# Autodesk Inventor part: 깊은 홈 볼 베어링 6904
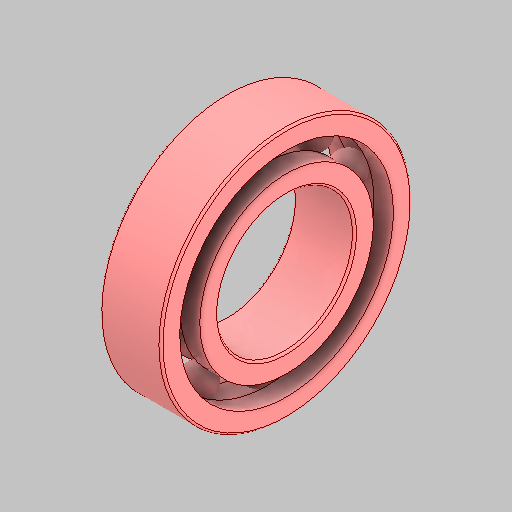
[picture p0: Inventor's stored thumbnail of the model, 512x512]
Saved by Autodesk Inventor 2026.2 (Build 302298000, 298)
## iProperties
Created: 2026-06
Part Number: 깊은 홈 볼 베어링 6904
Material: 강철, 연강
Description: 깊은 그루브 볼 베어링
Document SubType Name: Modeling
Designer: sec7
Density: 7.85 g/cm^3
Appearance: 기본값
Author: jhkim
Sending System: Autodesk Inventor 2027
Preprocessor: ST-DEVELOPER v20.1
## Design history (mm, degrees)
feature "Solid1"
feature "Solid1:1"
feature "Solid1:2"
feature "Solid1:3"
feature "Solid1:4"
feature "Solid1:5"
feature "Solid1:6"
feature "Solid1:7"
feature "Solid1:8"
feature "Solid1:9"
feature "Solid1:10"
feature "Solid1:11"
node "솔리드1"
node "솔리드2"
node "솔리드3"
node "솔리드4"
node "솔리드5"
node "솔리드6"
node "솔리드7"
node "솔리드8"
node "솔리드9"
node "솔리드10"
node "솔리드11"
node "솔리드12"
